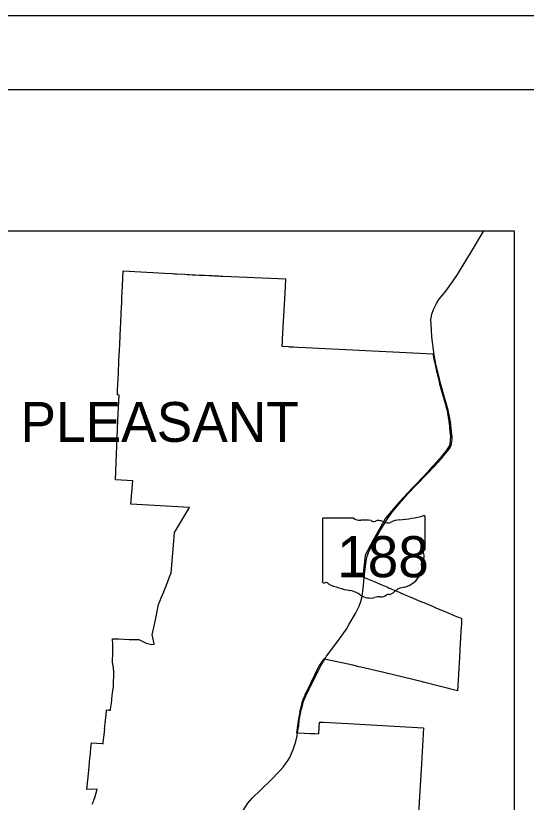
# Model space of a CAD drawing. Extents: x 0 to 34, y 0 to 22.
# Drawn here: x 12.32 to 15.78, y 16.68 to 22 of the extents above; entities that cross this region are included whole.
import ezdxf

# ---------------------------------------------------------------- set-up
doc = ezdxf.new("R2010")
doc.units = 0
for name, color, linetype in [('GM_X_Corporation', 7, 'Continuous'), ('GM_X_State_Route', 7, 'Continuous'), ('GM_X_State_Shield', 7, 'Continuous'), ('GM_X_Township_Text', 7, 'Continuous'), ('SH_Border', 7, 'Continuous'), ('SH_Cut_Line', 7, 'Continuous'), ('SH_Text', 7, 'Continuous')]:
    doc.layers.add(name, color=color, linetype=linetype)

msp = doc.modelspace()

# ---------------------------------------------------------------- linework, layer by layer
at = {"layer": 'GM_X_Corporation'}
msp.add_lwpolyline([(12.8407, 16.663), (12.8478, 16.6814), (12.851, 16.6905), (12.8594, 16.7155), (12.8671, 16.7408), (12.874, 16.7664), (12.8042, 16.7638), (12.8115, 16.8469), (12.8189, 16.9184), (12.8221, 16.9502), (12.828, 17.0093), (12.8314, 17.0447), (12.8348, 17.0785), (12.9063, 17.0736), (12.9139, 17.0726), (12.9151, 17.0827), (12.9205, 17.1323), (12.9251, 17.1738), (12.9231, 17.174), (12.9271, 17.2107), (12.9314, 17.2504), (12.9357, 17.2899), (12.9371, 17.3015), (12.9519, 17.3008), (12.9631, 17.3003), (12.9639, 17.3065), (12.9694, 17.347), (12.9723, 17.3681), (12.9738, 17.3797), (12.9781, 17.4151), (12.9833, 17.4577), (12.9839, 17.4622), (12.984, 17.4662), (12.9848, 17.5033), (12.9852, 17.5217), (12.9857, 17.5445), (12.9862, 17.5632), (12.9857, 17.5666), (12.9849, 17.5726), (12.9831, 17.5861), (12.9798, 17.611), (12.9783, 17.6226), (12.9768, 17.6337), (12.9777, 17.6489), (12.9786, 17.6681), (12.9785, 17.7172), (12.9785, 17.7412), (12.9785, 17.7432), (12.9783, 17.7832), (13.0178, 17.7818), (13.0902, 17.7794), (13.1267, 17.7782), (13.1287, 17.7781), (13.1553, 17.7772), (13.2002, 17.7551), (13.2053, 17.754), (13.244, 17.7454), (13.2586, 17.7473), (13.2585, 17.7483), (13.2485, 17.8001), (13.2467, 17.809), (13.2654, 17.9001), (13.2897, 18.0159), (13.3002, 18.0423), (13.3077, 18.0611), (13.3236, 18.1017), (13.3575, 18.1882), (13.3631, 18.2025), (13.3735, 18.2291), (13.3896, 18.4173), (13.3968, 18.5016), (13.4379, 18.5702), (13.498, 18.6724), (13.1017, 18.6938), (13.1151, 18.8525), (12.9969, 18.8591), (13.014, 19.2596), (13.0202, 19.3917), (13.0203, 19.3931), (13.0222, 19.4327), (13.0102, 19.4333), (13.0107, 19.4453), (13.0113, 19.4572), (13.0139, 19.5131), (13.0144, 19.5232), (13.0146, 19.5273), (13.0177, 19.5935), (13.0186, 19.6104), (13.0196, 19.6334), (13.0209, 19.6594), (13.0212, 19.6673), (13.0229, 19.7012), (13.0233, 19.7099), (13.0242, 19.7292), (13.0245, 19.7353), (13.0246, 19.7371), (13.0263, 19.7731), (13.0272, 19.7931), (13.0282, 19.813), (13.03, 19.8529), (13.0309, 19.8701), (13.0319, 19.8928), (13.033, 19.9148), (13.0333, 19.9216), (13.0335, 19.9251), (13.0338, 19.9327), (13.0357, 19.9727), (13.0364, 19.9875), (13.0364, 19.9875), (13.0399, 20.0622), (13.0402, 20.0673), (13.0413, 20.0912), (13.0434, 20.1349), (13.045, 20.1688), (13.0499, 20.2733), (13.3302, 20.2572), (13.3842, 20.2544), (13.398, 20.2535), (13.4114, 20.2527), (13.4122, 20.2527), (13.4662, 20.2499), (13.4841, 20.249), (13.4966, 20.2484), (13.5154, 20.2475), (13.5305, 20.2468), (13.5388, 20.2464), (13.5644, 20.2451), (13.5983, 20.2435), (13.6011, 20.2434), (13.6323, 20.2419), (13.654, 20.2408), (13.6662, 20.2402), (13.6886, 20.2392), (13.7001, 20.2386), (13.708, 20.2382), (13.7269, 20.2373), (13.9917, 20.2258), (14.0499, 20.2232), (14.1487, 20.2186), (14.1458, 20.163), (14.1266, 19.8132), (14.1259, 19.7997), (14.1257, 19.7948), (14.124, 19.7629), (14.1683, 19.7606), (14.1761, 19.7602), (14.1783, 19.7601), (14.1827, 19.7598), (14.1883, 19.7596), (14.2022, 19.7588), (14.2295, 19.7574), (14.2295, 19.7574), (14.2839, 19.7546), (15.0091, 19.7182), (15.1463, 19.7113), (15.1553, 19.6637), (15.1564, 19.6577), (15.1582, 19.6482), (15.1679, 19.6046), (15.1707, 19.5923), (15.1722, 19.5858), (15.1877, 19.5213), (15.1913, 19.5056), (15.1915, 19.5049), (15.1928, 19.4993), (15.2015, 19.469), (15.2145, 19.4239), (15.219, 19.4097), (15.22, 19.4062), (15.2303, 19.3697), (15.2345, 19.3551), (15.2418, 19.3291), (15.2518, 19.2676), (15.2532, 19.2591), (15.2544, 19.2517), (15.2553, 19.2437), (15.2582, 19.2161), (15.2588, 19.2112), (15.2592, 19.2077), (15.2612, 19.187), (15.2632, 19.1663), (15.2643, 19.1552), (15.2646, 19.1516), (15.2605, 19.1006), (15.2601, 19.0958), (15.235, 19.0542), (15.2211, 19.0377), (15.1946, 19.0066), (15.1799, 18.9893), (15.175, 18.9834), (15.1436, 18.9488), (15.121, 18.9239), (15.1138, 18.916), (15.0792, 18.8799), (15.0303, 18.828), (15.0147, 18.8114), (15.0086, 18.805), (14.9174, 18.708), (14.8258, 18.5995), (14.7424, 18.4497), (14.6872, 18.348), (14.6715, 18.2019), (14.672, 18.2017), (14.683, 18.1971), (14.7024, 18.1889), (14.7476, 18.1699), (14.7842, 18.1544), (14.7936, 18.1504), (14.7936, 18.1504), (14.8173, 18.1404), (14.8382, 18.1316), (14.8505, 18.1265), (14.8643, 18.1206), (14.8836, 18.1125), (14.9296, 18.0931), (14.9367, 18.0901), (14.9407, 18.0884), (14.9485, 18.0851), (14.9517, 18.0838), (14.9742, 18.0743), (14.9959, 18.0651), (15.0327, 18.0496), (15.0695, 18.0341), (15.0844, 18.0278), (15.1154, 18.0147), (15.1154, 18.0148), (15.1468, 18.0015), (15.1654, 17.9936), (15.1826, 17.9864), (15.2232, 17.9693), (15.3063, 17.9342), (15.3182, 17.9292), (15.3408, 17.9197), (15.3407, 17.9181), (15.3386, 17.8829), (15.336, 17.8401), (15.3353, 17.8276), (15.3284, 17.7139), (15.325, 17.6561), (15.3114, 17.4314), (15.0818, 17.4895), (15.0797, 17.49), (15.0753, 17.4912), (14.8138, 17.554), (14.6576, 17.5915), (14.6442, 17.5944), (14.6032, 17.6035), (14.53, 17.6198), (14.4218, 17.6438), (14.4124, 17.6457), (14.4101, 17.6462), (14.4072, 17.6468), (14.3878, 17.6174), (14.3788, 17.6037), (14.3632, 17.5757), (14.3631, 17.5756), (14.3442, 17.5363), (14.333, 17.5128), (14.325, 17.4962), (14.3183, 17.4822), (14.317, 17.4796), (14.3149, 17.4753), (14.3046, 17.4537), (14.2901, 17.4236), (14.2866, 17.4163), (14.2798, 17.4022), (14.2789, 17.4001), (14.2687, 17.3763), (14.2686, 17.3759), (14.2606, 17.3574), (14.2594, 17.3521), (14.2532, 17.3269), (14.2491, 17.3103), (14.2468, 17.3012), (14.2458, 17.2949), (14.2448, 17.2894), (14.2444, 17.2866), (14.2369, 17.2424), (14.234, 17.2264), (14.2297, 17.1979), (14.2267, 17.1773), (14.2221, 17.1468), (14.2242, 17.1467), (14.2342, 17.1461), (14.3143, 17.1428), (14.3462, 17.1413), (14.3741, 17.14), (14.3742, 17.1415), (14.3777, 17.2199), (14.4037, 17.2184), (14.5717, 17.209), (14.8848, 17.1916), (15.0824, 17.1805), (15.0677, 16.937), (15.0474, 16.6019)], dxfattribs=at)
at = {"layer": 'GM_X_State_Route'}
for points in [[(14.6814, 18.2011), (14.6919, 18.2908), (14.6972, 18.323), (14.7015, 18.342), (14.7054, 18.3543), (14.7103, 18.3663), (14.7244, 18.3957), (14.7453, 18.4365), (14.786, 18.5113), (14.8341, 18.5893), (14.8688, 18.6368), (14.9313, 18.7125), (14.9751, 18.7612), (15.0377, 18.8283), (15.1016, 18.8942), (15.1562, 18.9508), (15.2047, 19.0042), (15.2301, 19.0343), (15.2463, 19.055), (15.2575, 19.0714), (15.2641, 19.0829), (15.2669, 19.089), (15.2724, 19.1031), (15.2749, 19.1156), (15.276, 19.1344), (15.2755, 19.1476), (15.2722, 19.1871), (15.2649, 19.2517), (15.259, 19.2876), (15.2484, 19.3305), (15.2383, 19.3716), (15.2292, 19.4013), (15.1997, 19.5036), (15.1832, 19.5709), (15.1666, 19.6424), (15.1553, 19.7042), (15.138, 19.8278), (15.1335, 19.913), (15.1329, 19.9425), (15.1393, 19.9796), (15.1495, 20.0123), (15.1694, 20.0533), (15.1869, 20.0801), (15.2334, 20.1353), (15.2825, 20.2066), (15.3119, 20.2489), (15.4069, 20.405), (15.4911, 20.5443)], [(14.5795, 17.8826), (14.6213, 17.9549), (14.6466, 18.003), (14.658, 18.0344), (14.6668, 18.0687), (14.6735, 18.1243), (14.6777, 18.1698), (14.6814, 18.2011)], [(14.4211, 17.6575), (14.4265, 17.6665), (14.4951, 17.7583), (14.5603, 17.8493), (14.5795, 17.8826)], [(14.3701, 17.5643), (14.3887, 17.6039), (14.4211, 17.6575)], [(14.2412, 17.2313), (14.2496, 17.2764), (14.2552, 17.3025), (14.2624, 17.3324), (14.2707, 17.3617), (14.2945, 17.4177), (14.3673, 17.5584), (14.3701, 17.5643)], [(14.2262, 17.1272), (14.2302, 17.1497), (14.2374, 17.1938), (14.2412, 17.2313)], [(13.9905, 16.77), (14.0424, 16.8184), (14.111, 16.8893), (14.1326, 16.9144), (14.1539, 16.9444), (14.1659, 16.9627), (14.1776, 16.9802), (14.2, 17.0334), (14.2191, 17.0883), (14.2262, 17.1272)], [(13.6994, 15.8592), (13.7697, 16.2099), (13.8033, 16.4175), (13.8298, 16.5452), (13.8373, 16.5706), (13.8493, 16.5988), (13.8584, 16.6171), (13.8725, 16.6382), (13.8938, 16.6706), (13.9231, 16.7036), (13.9814, 16.7615), (13.9905, 16.77)]]:
    msp.add_lwpolyline(points, dxfattribs=at)
at = {"layer": 'GM_X_State_Shield'}
for p, q in [((14.3976, 18.5922), (14.3976, 18.17)), ((14.608, 18.5994), (14.4044, 18.5994)), ((15.0928, 18.3891), (15.0928, 18.6099)), ((15.0927, 18.3891), (15.0928, 18.3891))]:
    msp.add_line(p, q, dxfattribs=at)
for centre, major_axis, start_param, end_param in [((14.4056, 18.5931), (0.00805, 0), 1.712693, 3.28349), ((14.6565, 18.6484), (0.0781, 0), 4.042523, 4.731795), ((14.6824, 18.3624), (0.2804, 0), 1.404758, 1.657858), ((14.7461, 18.5953), (0.0225, 0), 3.836095, 5.185415), ((14.7792, 18.5465), (0.0469, 0), 0.950623, 2.079405), ((14.9392, 18.4705), (0.1483, 0), 1.699011, 2.107814), ((14.8452, 19.1749), (0.7373, 0), 4.814394, 5.042369), ((15.0851, 18.6108), (0.00774, 0), 6.141152, 7.989035), ((14.8397, 18.6134), (0.0564, 0), 4.081561, 5.145723), ((15.091, 18.3729), (0.012, 0), 1.883978, 3.671073), ((15.0148, 18.345), (0.0719, 0), 5.934695, 6.695948), ((15.0846, 18.3882), (0.00828, 0), 5.05454, 6.418171), ((15.1205, 18.2967), (0.0523, 0), 2.387724, 3.262537), ((14.8865, 18.2686), (0.1844, 0), 5.101752, 6.440018), ((14.4056, 18.1691), (0.00813, 0), 3.00124, 4.508301), ((14.4069, 18.2123), (0.062, 0), 4.665946, 4.897461), ((14.4195, 18.1457), (0.0224, 0), 0.519207, 1.627899), ((14.7018, 18.525), (0.5324, 0), 4.195997, 4.488961), ((14.5431, 17.9804), (0.1666, 0), 0.823519, 1.323587), ((14.8363, 18.1291), (0.0596, 0), 4.937069, 5.64225), ((14.9642, 18.0515), (0.101, 0), 1.647645, 2.488434), ((14.7233, 18.1436), (0.1057, 0), 4.026481, 4.996735), ((14.7843, 17.9976), (0.0869, 0), 1.495662, 1.94098), ((14.7921, 18.112), (0.0563, 0), 4.691044, 5.507374), ((14.843, 18.0711), (0.0159, 0), 1.147584, 2.315152)]:
    msp.add_ellipse(centre, major_axis=major_axis, ratio=0.8, start_param=start_param, end_param=end_param, dxfattribs=at)
at = {"layer": 'SH_Border'}
msp.add_lwpolyline([(1.5, 21.5), (33.5, 21.5), (33.5, 0.5), (1.5, 0.5)], close=True, dxfattribs=at)
at = {"layer": 'SH_Cut_Line'}
msp.add_lwpolyline([(0, 0), (34, 0), (34, 22), (0, 22)], close=True, dxfattribs=at)
at = {"layer": 'SH_Text'}
msp.add_lwpolyline([(2.5702, 20.5443), (15.6971, 20.5443), (15.6971, 8.9902), (2.5702, 8.9902)], close=True, dxfattribs=at)

# ---------------------------------------------------------------- texts
at = {"layer": 'GM_X_State_Shield'}
msp.add_text('188', height=0.27809, dxfattribs=at).set_placement((14.498, 18.1998))
at = {"layer": 'GM_X_Township_Text'}
msp.add_text('PLEASANT', height=0.26966, rotation=0, dxfattribs=at).set_placement((12.3543, 19.116))

doc.saveas('drawing.dxf')
